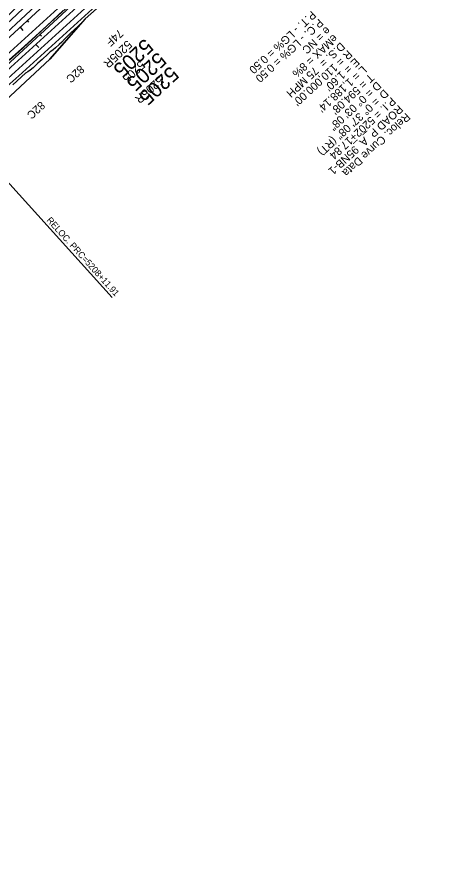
# Model space of a CAD drawing. Extents: x 2160876 to 2175990, y 601436 to 618246.
# Drawn here: x 2169705 to 2170516, y 609834 to 611423 of the extents above; entities that cross this region are included whole.
import ezdxf

# ---------------------------------------------------------------- set-up
doc = ezdxf.new("R2010")
doc.units = 0
for name, color, linetype in [('BNDY-ADJ', 7, 'Continuous'), ('BNDY-ADJ-TXT', 7, 'Continuous'), ('EX-UTIL-ELEC-TXT', 7, 'Continuous'), ('GN_Transparent 80', 7, 'Continuous'), ('RD_DTM_Major2', 7, 'Continuous'), ('RD_EX_BldgApp_Sign', 7, 'Continuous'), ('RD_EX_BldgApp_Steps', 7, 'Continuous'), ('RD_EX_DV_TX_Prop', 7, 'Continuous'), ('RD_EX_Fence_Gate', 7, 'Continuous'), ('RD_EX_RW', 7, 'Continuous'), ('RD_HC_Cl', 7, 'Continuous'), ('RD_HC_Data_Tic', 7, 'Continuous'), ('RD_HC_TX_Sta50', 7, 'Continuous'), ('RD_TX_RoadID', 7, 'Continuous')]:
    doc.layers.add(name, color=color, linetype=linetype)

msp = doc.modelspace()

# ---------------------------------------------------------------- linework, layer by layer
at = {"layer": 'BNDY-ADJ'}
msp.add_line((2172239.9, 613739.9), (2163704.8, 605858.6), dxfattribs=at)
at = {"layer": 'BNDY-ADJ-TXT'}
for centre, start, end in [((2245020.2, 531286.6), 132.719474, 133.338342), ((2095835.3, 692846.5), 312.100607, 312.719474)]:
    msp.add_arc(centre, 110000, start, end, dxfattribs=at)
at = {"layer": 'EX-UTIL-ELEC-TXT'}
for centre, radius, start, end in [((2245020.2, 531286.6), 110041.3, 132.719474, 133.338342), ((2245020.2, 531286.6), 110040.3, 132.719474, 133.338342), ((2245020.2, 531286.6), 110012, 132.719474, 133.338342), ((2245020.2, 531286.6), 110000, 132.719474, 133.338342), ((2245020.2, 531286.6), 109988, 132.719474, 133.338342), ((2095835.3, 692846.5), 109988, 312.100607, 312.719474), ((2095835.3, 692846.5), 110000, 312.100607, 312.719474), ((2095835.3, 692846.5), 110012, 312.100607, 312.719474)]:
    msp.add_arc(centre, radius, start, end, dxfattribs=at)
at = {"layer": 'GN_Transparent 80'}
for radius in [110026.3, 110024]:
    msp.add_arc((2245020.2, 531286.6), radius, 132.719474, 133.338342, dxfattribs=at)
at = {"layer": 'RD_DTM_Major2'}
msp.add_line((2169710.5, 611404.2), (2169715.9, 611398.4), dxfattribs=at)
at = {"layer": 'RD_EX_BldgApp_Sign'}
msp.add_arc((2245020.2, 531286.6), 109966, 132.719474, 133.338342, dxfattribs=at)
at = {"layer": 'RD_EX_BldgApp_Steps'}
for p, q in [((2172672.7, 614139.6), (2163700.6, 605854.7)), ((2169821.3, 611458.6), (2165682.4, 607636.8)), ((2169723.9, 611416.6), (2169726.6, 611413.7)), ((2169747.8, 611390.8), (2169750.5, 611387.9))]:
    msp.add_line(p, q, dxfattribs=at)
at = {"layer": 'RD_EX_Fence_Gate'}
msp.add_lwpolyline([(2169947.4, 611516.2), (2169906.8, 611486.5), (2169832.2, 611419.8), (2169766.1, 611344.1), (2169692.9, 611276), (2169621.4, 611206), (2169538.3, 611148.5), (2169467, 611078.3), (2169391.8, 611012.4), (2169318.6, 610944.2), (2169284.7, 610907.2), (2169174, 610806.1), (2169099.5, 610739.3), (2169025.5, 610672), (2168948.7, 610607.8), (2168874.4, 610540.9), (2168798.4, 610475.8), (2168741.5, 610390), (2168667.6, 610322.7), (2168592.4, 610252), (2168544.5, 610187.1)], dxfattribs=at)
at = {"layer": 'RD_EX_RW'}
for points in [[(2169690.7, 611342.5), (2169709, 611358.8), (2169731.8, 611380.3), (2169750.1, 611397.1), (2169771.3, 611416.6), (2169791.5, 611435.3)], [(2168965.7, 610622), (2169025.5, 610672), (2169099.5, 610739.3), (2169174, 610806.1), (2169284.7, 610907.2), (2169318.6, 610944.2), (2169391.8, 611012.4), (2169467, 611078.3), (2169538.3, 611148.5), (2169621.4, 611206), (2169692.9, 611276), (2169766.1, 611344.1), (2169824.9, 611411.5)], [(2169824.9, 611411.5), (2169818.7, 611405.8), (2169805.3, 611393.7), (2169797.6, 611385.8), (2169794, 611382.1), (2169788.6, 611376.5), (2169783.9, 611372.1), (2169776.9, 611365.7), (2169772.7, 611361.6), (2169769.9, 611359.9), (2169766.7, 611358), (2169762.5, 611353.7), (2169751.7, 611343.7), (2169743.6, 611336.7), (2169739.7, 611332.7), (2169734.8, 611328.1), (2169729.7, 611323.7), (2169725, 611320.6), (2169720.8, 611318.2), (2169697, 611296.4)]]:
    msp.add_lwpolyline(points, dxfattribs=at)
at = {"layer": 'RD_HC_Cl'}
msp.add_line((2169740.2, 611372.2), (2169745.5, 611366.3), dxfattribs=at)
at = {"layer": 'RD_HC_TX_Sta50'}
msp.add_line((2169883, 610898), (2169583.1, 611230), dxfattribs=at)
at = {"layer": 'RD_TX_RoadID'}
for centre, radius, start, end in [((2245020.2, 531286.6), 110024, 132.719474, 133.338342), ((2245020.2, 531286.6), 109978, 132.719474, 133.338342), ((2095835.3, 692846.5), 109978, 312.100607, 312.719474), ((2095835.3, 692846.5), 110022, 312.100607, 312.719474)]:
    msp.add_arc(centre, radius, start, end, dxfattribs=at)

# ---------------------------------------------------------------- texts
at = {"layer": 'RD_EX_BldgApp_Steps'}
for p in [(2169943.9, 611384.6), (2169968.4, 611359.3), (2169991.7, 611332.9)]:
    msp.add_text('5205', height=28, rotation=222.7195, dxfattribs=at).set_placement(p)
at = {"layer": 'RD_EX_DV_TX_Prop'}
msp.add_text('5205', height=16, rotation=222.7195, dxfattribs=at).set_placement((2169935.7, 611342.7))
at = {"layer": 'RD_EX_Fence_Gate'}
for s, p in [('74F', (2169895.6, 611401.4)), ('82C', (2169822.6, 611334.3)), ('82C', (2169749.1, 611266.5))]:
    msp.add_text(s, height=15, rotation=222.2032, dxfattribs=at).set_placement(p)
at = {"layer": 'RD_HC_Data_Tic'}
for rotation, p in [(223.1759, (2169911.2, 611381)), (222.2631, (2169970.6, 611314))]:
    msp.add_text('5205R', height=16, rotation=rotation, dxfattribs=at).set_placement(p)
at = {"layer": 'RD_HC_TX_Sta50'}
for s, height, rotation, p in [('P.T. - LG% = 0.50', 15, 222.7195, (2170256.4, 611435.9)), ('P.C. - LG% = 0.50', 15, 222.7195, (2170270, 611421.2)), ('e = NC', 15, 222.7195, (2170283.6, 611406.5)), ('eMAX = 8%', 15, 222.7195, (2170297.1, 611391.8)), ('D.S. =  75 MPH', 15, 222.7195, (2170310.7, 611377.1)), ("R = 110,000.00'", 15, 222.7195, (2170324.3, 611362.4)), ("E = 1.60'", 15, 222.7195, (2170337.8, 611347.7)), ("L = 1,188.14'", 15, 222.7195, (2170351.4, 611333)), ("T = 594.08'", 15, 222.7195, (2170365, 611318.3)), ('D = 0° 03\' 08"', 15, 222.7195, (2170378.5, 611303.6)), ('D', 15, 222.7195, (2170392.1, 611288.9)), ('    = 0° 37\' 08" (RT)', 15, 222.7195, (2170392.1, 611288.9)), ('P.I. = 5202+17.84', 15, 222.7195, (2170405.7, 611274.2)), ('ROAD P_A_95NB-1', 15, 222.7195, (2170419.2, 611259.5)), ('Reloc. Curve Data', 15, 222.7195, (2170432.8, 611244.8)), ('RELOC. PRC=5208+11.91', 12, 312.1006, (2169759.4, 611042))]:
    msp.add_text(s, height=height, rotation=rotation, dxfattribs=at).set_placement(p)

doc.saveas('drawing.dxf')
